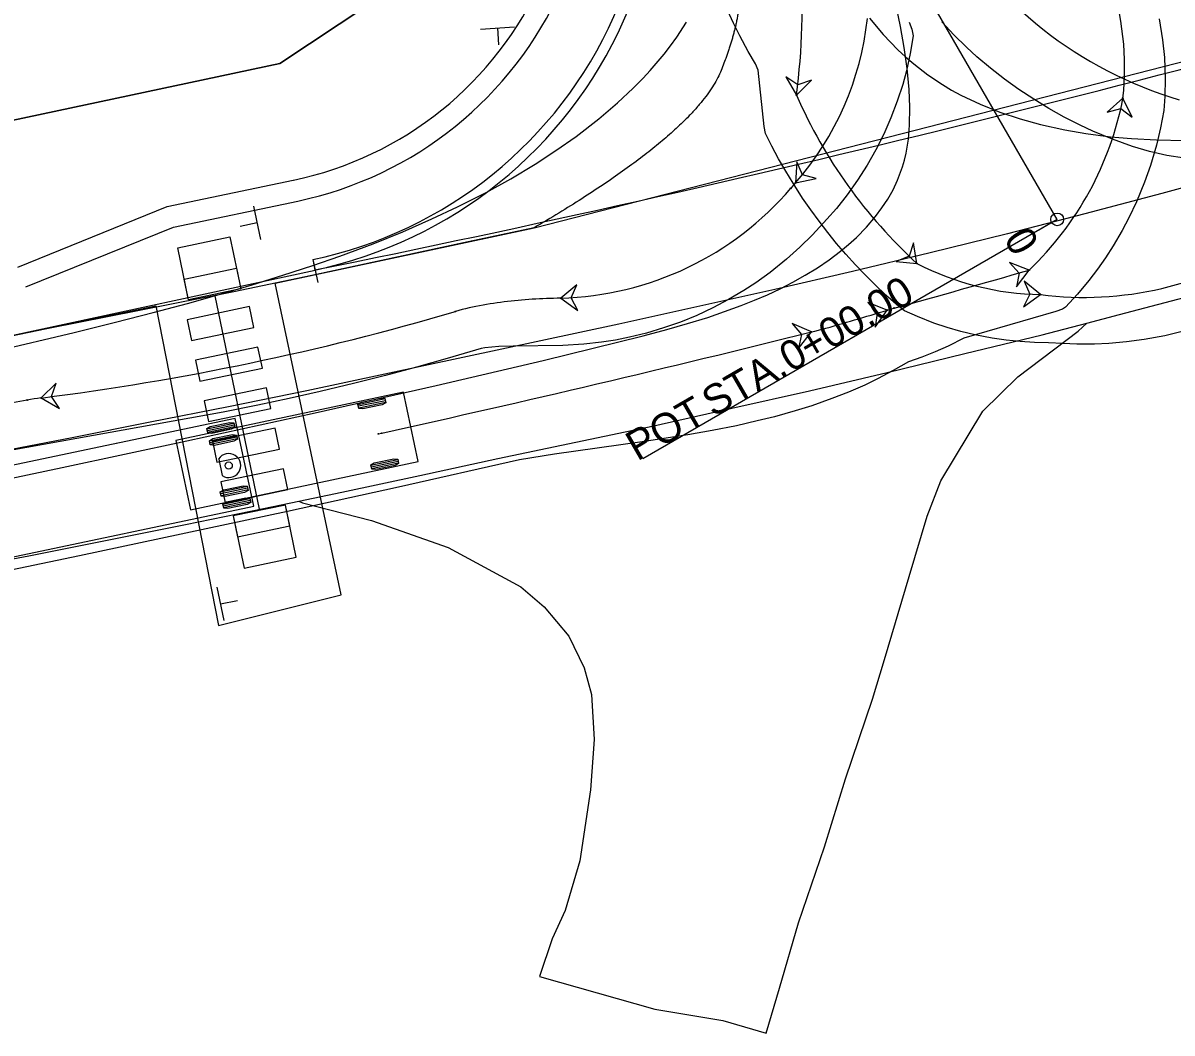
# Model space of a CAD drawing. Extents: x 208278 to 2196496, y 417130 to 637870.
# Drawn here: x 209106 to 209214, y 417248.4 to 417343.4 of the extents above; entities that cross this region are included whole.
import ezdxf

# ---------------------------------------------------------------- set-up
doc = ezdxf.new("R2010")
doc.units = 0
for name, color, linetype in [('BR_P_Beam', 7, 'Continuous'), ('DR_P_Ditch', 7, 'Continuous'), ('DR_P_Filter_Fabric_Fence', 7, 'Continuous'), ('DR_P_Trench_Drain', 7, 'Continuous'), ('LT_P_Conduit', 7, 'Continuous'), ('PM_P_Channelizing_Line', 7, 'Continuous'), ('PM_P_CL_Dashed', 7, 'Continuous'), ('PM_P_Crosswalk', 7, 'Continuous'), ('PM_P_Edge_Line', 7, 'Continuous'), ('PV_P_Curb', 7, 'Continuous'), ('RD_P_Concrete_Barrier', 7, 'Continuous'), ('RD_P_Fence', 7, 'Continuous'), ('RD_P_Gate', 7, 'Continuous'), ('RW_P_PARCEL', 7, 'Continuous'), ('UT_P_Sanitary', 7, 'Continuous'), ('UT_P_Water', 7, 'Continuous'), ('XS_P_Section', 7, 'Continuous')]:
    doc.layers.add(name, color=color, linetype=linetype)

msp = doc.modelspace()

# ---------------------------------------------------------------- linework, layer by layer
at = {"layer": 'BR_P_Beam'}
msp.add_arc((209125.04, 417360.3), 41, 281.847, 30.029, dxfattribs=at)
at = {"layer": 'DR_P_Ditch'}
msp.add_line((209203.23, 417324.93), (209161.75, 417396.69), dxfattribs=at)
at = {"layer": 'DR_P_Filter_Fabric_Fence'}
for points in [[(209103.37, 417312.55), (209110.83, 417314.3), (209114.71, 417315.26), (209118.26, 417316.17), (209121.48, 417317.04), (209124.69, 417317.94), (209127.57, 417318.79), (209130.43, 417319.68), (209133.28, 417320.61), (209135.8, 417321.49), (209138.93, 417322.65), (209141.71, 417323.77), (209144.46, 417324.97), (209146.87, 417326.1), (209149.55, 417327.46), (209151.88, 417328.75), (209154.17, 417330.13), (209156.12, 417331.4), (209158.03, 417332.74), (209160.14, 417334.38), (209161.91, 417335.89), (209163.37, 417337.26), (209164.3, 417338.21), (209164.98, 417338.94), (209166.28, 417340.47), (209166.89, 417341.25), (209167.47, 417342.06), (209168.39, 417343.46)], [(209189.33, 417343.46), (209189.56, 417342.83), (209189.7, 417342.18), (209189.42, 417340.54), (209189.06, 417338.91), (209188.71, 417337.62), (209188.2, 417336.04), (209187.6, 417334.48), (209186.93, 417332.95), (209186.19, 417331.47), (209185.36, 417330.02), (209184.47, 417328.61), (209183.5, 417327.25), (209182.47, 417325.95), (209181.59, 417324.94), (209180.23, 417323.48), (209179.04, 417322.31), (209177.8, 417321.19), (209176.24, 417319.94), (209174.89, 417318.97), (209173.77, 417318.24), (209172.34, 417317.39), (209170.87, 417316.61), (209169.36, 417315.91), (209167.81, 417315.28), (209166.24, 417314.73), (209164.64, 417314.25), (209163.03, 417313.85), (209161.72, 417313.59), (209160.4, 417313.39), (209158.75, 417313.2), (209156.75, 417313.08), (209152.08, 417313.03), (209150.75, 417312.97), (209149.42, 417312.87), (209149.1, 417312.8), (209145.9, 417311.85), (209143.01, 417311.04), (209140.11, 417310.27), (209137.21, 417309.53), (209133.96, 417308.76), (209131.04, 417308.1), (209128.1, 417307.48), (209124.83, 417306.82), (209104.82, 417303.22)], [(209178.64, 417328.37), (209180.57, 417328.77), (209179.28, 417329.11), (209178.75, 417330.34), (209178.64, 417328.37)], [(209178.64, 417328.37), (209178.42, 417328.12), (209178.2, 417327.86)], [(209156.56, 417317.53), (209158.16, 417316.38), (209157.54, 417317.56), (209158.08, 417318.78), (209156.56, 417317.53)], [(209156.56, 417317.53), (209156.22, 417317.52), (209155.89, 417317.51), (209155.56, 417317.5), (209155.22, 417317.49), (209154.89, 417317.47), (209154.56, 417317.46), (209154.22, 417317.44), (209153.89, 417317.42), (209153.56, 417317.4), (209153.23, 417317.37), (209152.89, 417317.35), (209152.56, 417317.32), (209152.23, 417317.29), (209151.9, 417317.25), (209151.57, 417317.22), (209151.24, 417317.18), (209150.91, 417317.13), (209150.58, 417317.09), (209150.25, 417317.04), (209149.92, 417316.99), (209149.59, 417316.93), (209149.26, 417316.88), (209148.93, 417316.81), (209148.6, 417316.75), (209148.28, 417316.68), (209147.95, 417316.61), (209147.63, 417316.53), (209147.31, 417316.45), (209146.98, 417316.36), (209146.66, 417316.27)], [(209107.73, 417308.15), (209109.44, 417307.15), (209108.71, 417308.27), (209109.13, 417309.54), (209107.73, 417308.15)], [(209107.73, 417308.15), (209107.4, 417308.1), (209107.07, 417308.06), (209106.74, 417308.01), (209106.41, 417307.95)]]:
    msp.add_lwpolyline(points, dxfattribs=at)
for points in [[(209178.64, 417328.37), (209180.57, 417328.77), (209179.28, 417329.11), (209178.75, 417330.34)], [(209156.56, 417317.53), (209158.16, 417316.38), (209157.54, 417317.56), (209158.08, 417318.78)], [(209107.73, 417308.15), (209109.44, 417307.15), (209108.71, 417308.27), (209109.13, 417309.54)]]:
    msp.add_lwpolyline(points, close=True, dxfattribs=at)
for centre in [(209178.2, 417327.86), (209178.2, 417327.86), (209178.64, 417328.37), (209178.64, 417328.37), (209156.56, 417317.53), (209156.56, 417317.53), (209146.66, 417316.27), (209146.66, 417316.27), (209107.73, 417308.15), (209107.73, 417308.15), (209106.41, 417307.95), (209106.41, 417307.95)]:
    msp.add_circle(centre, 0.0417, dxfattribs=at)
for centre, radius, start, end in [((209157.52, 417346.8), 28.03, 318.8875, 353.8854), ((209155.75, 417347.05), 29.53, 271.5616, 319.4785), ((209076.23, 417556.4), 250.25, 277.2308, 286.3462), ((210285.7, 410968.14), 6448.56, 100.537372, 101.036132)]:
    msp.add_arc(centre, radius, start, end, dxfattribs=at)
at = {"layer": 'DR_P_Trench_Drain'}
msp.add_lwpolyline([(209215.18, 417330.69), (209213.53, 417330.94), (209211.91, 417331.31), (209210.31, 417331.78), (209208.43, 417332.47), (209206.59, 417333.24), (209205.38, 417333.8), (209203.89, 417334.55), (209202.44, 417335.36), (209201.02, 417336.23), (209199.63, 417337.15), (209198.28, 417338.13), (209196.96, 417339.16), (209195.69, 417340.23), (209194.71, 417341.13), (209193.51, 417342.29), (209192.37, 417343.5)], dxfattribs=at)
msp.add_arc((209225.78, 417373.22), 38.67, 210.338, 253.3438, dxfattribs=at)
at = {"layer": 'LT_P_Conduit'}
for points in [[(209214.98, 417314.38), (209213.36, 417313.99), (209211.4, 417313.63), (209209.74, 417313.41), (209208.08, 417313.27), (209206.75, 417313.21), (209205.08, 417313.2), (209203.75, 417313.25), (209202.42, 417313.34), (209201.09, 417313.37), (209199.76, 417313.44), (209198.43, 417313.57), (209197.11, 417313.76), (209195.48, 417314.08), (209194.18, 417314.39), (209192.9, 417314.76), (209191.64, 417315.19), (209190.09, 417315.79), (209188.87, 417316.34), (209188.34, 417316.74), (209187.34, 417317.62), (209186.36, 417318.53), (209185.18, 417319.71), (209184.26, 417320.67), (209183.37, 417321.66), (209182.5, 417322.67), (209181.66, 417323.71), (209180.85, 417324.76), (209180.06, 417325.84), (209179.3, 417326.94), (209178.4, 417328.34), (209177.71, 417329.48), (209177.04, 417330.63), (209176.41, 417331.81), (209175.81, 417333), (209175.69, 417333.65), (209175.13, 417338.96), (209174.87, 417339.57), (209174.19, 417340.72), (209173.4, 417342.18), (209172.81, 417343.38), (209172.24, 417344.59)], [(209185.58, 417343.86), (209186.87, 417342.32), (209187.55, 417341.59), (209188.25, 417340.88), (209188.98, 417340.2), (209189.74, 417339.55), (209191.06, 417338.53), (209192.44, 417337.6), (209193.3, 417337.09), (209194.18, 417336.62), (209195.99, 417335.76), (209197.84, 417335.01), (209199.74, 417334.38), (209201.66, 417333.84), (209203.94, 417333.34), (209205.91, 417333), (209208.23, 417332.7), (209210.22, 417332.53), (209212.55, 417332.41), (209215.22, 417332.36)], [(209178.72, 417336.61), (209180.12, 417338.01), (209178.85, 417337.59), (209177.73, 417338.32), (209178.72, 417336.61)], [(209190.04, 417320.79), (209189.71, 417322.74), (209189.32, 417321.46), (209188.08, 417320.97), (209190.04, 417320.79)], [(209201.65, 417317.87), (209200.12, 417319.11), (209200.67, 417317.89), (209200.06, 417316.7), (209201.65, 417317.87)]]:
    msp.add_lwpolyline(points, dxfattribs=at)
for points in [[(209178.72, 417336.61), (209180.12, 417338.01), (209178.85, 417337.59), (209177.73, 417338.32)], [(209190.04, 417320.79), (209189.71, 417322.74), (209189.32, 417321.46), (209188.08, 417320.97)], [(209201.65, 417317.87), (209200.12, 417319.11), (209200.67, 417317.89), (209200.06, 417316.7)]]:
    msp.add_lwpolyline(points, close=True, dxfattribs=at)
for centre in [(209178.72, 417336.61), (209178.72, 417336.61), (209190.04, 417320.79), (209190.04, 417320.79), (209201.65, 417317.87), (209201.65, 417317.87)]:
    msp.add_circle(centre, 0.0417, dxfattribs=at)
for centre, radius, start, end in [((209117.29, 417344.79), 61.97, 352.412, 16.2407), ((209221.9, 417355.55), 47.15, 203.6848, 227.4956), ((209205.77, 417349.42), 31.82, 262.5686, 303.9316), ((209202.11, 417344.17), 26.31, 242.7082, 269.0122)]:
    msp.add_arc(centre, radius, start, end, dxfattribs=at)
at = {"layer": 'PM_P_Channelizing_Line'}
for points in [[(209125.46, 417323.28), (209126.49, 417318.39), (209121.59, 417317.36), (209120.57, 417322.26)], [(209126.08, 417320.34), (209126.49, 417318.39), (209121.59, 417317.36), (209121.18, 417319.32)], [(209131.7, 417293.17), (209130.69, 417298.07), (209125.79, 417297.05), (209126.81, 417292.16)], [(209131.09, 417296.11), (209130.69, 417298.07), (209125.79, 417297.05), (209126.2, 417295.09)]]:
    msp.add_lwpolyline(points, close=True, dxfattribs=at)
at = {"layer": 'PM_P_CL_Dashed'}
for points in [[(209121.85, 417313.54), (209127.73, 417314.77), (209127.32, 417316.73), (209121.44, 417315.5)], [(209122.65, 417309.73), (209128.52, 417310.96), (209128.11, 417312.92), (209122.24, 417311.69)], [(209123.45, 417305.92), (209129.32, 417307.15), (209128.91, 417309.11), (209123.04, 417307.88)], [(209124.24, 417302.11), (209130.12, 417303.34), (209129.71, 417305.3), (209123.83, 417304.07)], [(209125.04, 417298.3), (209130.91, 417299.53), (209130.5, 417301.49), (209124.63, 417300.26)]]:
    msp.add_lwpolyline(points, close=True, dxfattribs=at)
at = {"layer": 'PM_P_Crosswalk'}
for p, q in [((209149.02, 417342.83), (209152.22, 417343.02)), ((209150.62, 417342.93), (209150.72, 417341.33)), ((209150.62, 417342.93), (209150.62, 417342.93)), ((209127.69, 417326.17), (209128.35, 417323.03)), ((209128.02, 417324.6), (209126.45, 417324.27)), ((209128.02, 417324.6), (209128.02, 417324.6)), ((209124.93, 417287.21), (209124.28, 417290.35)), ((209124.6, 417288.78), (209126.17, 417289.11)), ((209124.6, 417288.78), (209124.6, 417288.78))]:
    msp.add_line(p, q, dxfattribs=at)
at = {"layer": 'PM_P_Edge_Line'}
msp.add_lwpolyline([(209093.86, 417513.4), (209102.11, 417463.85), (209121.09, 417416.38), (209142.14, 417379.63), (209146.67, 417363.53), (209141.31, 417347.02), (209130.17, 417339.58), (209102, 417333.59), (209104.94, 417313.99), (209118.52, 417316.8), (209124.41, 417286.75), (209135.92, 417289.64), (209129.73, 417318.94), (209154.07, 417324.14), (209248.91, 417348.5), (209255.78, 417350.71), (209251.98, 417364.94), (209222.73, 417364.32), (209215.99, 417362.52), (209193.28, 417384.78), (209187.97, 417395.34), (209174.69, 417434.86), (209154.88, 417469.95), (209142.09, 417520.32)], dxfattribs=at)
at = {"layer": 'PV_P_Curb'}
msp.add_lwpolyline([(209220.31, 417329.34), (209213.07, 417327.38), (209205.82, 417325.47), (209198.56, 417323.58), (209191.28, 417321.8), (209183.99, 417320.03), (209176.68, 417318.34), (209169.36, 417316.7), (209162.04, 417315.07), (209154.7, 417313.53), (209147.37, 417311.96), (209140.03, 417310.39), (209132.7, 417308.82), (209125.35, 417307.32), (209117.99, 417305.86), (209110.64, 417304.41), (209103.27, 417303)], dxfattribs=at)
at = {"layer": 'RD_P_Concrete_Barrier'}
for points in [[(209154.07, 417324.14), (209147.85, 417322.81), (209133.18, 417319.66), (209125.84, 417318.12), (209111.13, 417315.21), (209103.77, 417313.77), (209081.63, 417309.75), (209074.24, 417308.49), (209066.84, 417307.25), (209059.45, 417305.98), (209029.89, 417300.86), (209022.5, 417299.55), (208992.99, 417294.18), (208985.61, 417292.83), (208978.22, 417291.53), (208948.67, 417286.39), (208941.28, 417285.1), (208904.33, 417278.7), (208896.95, 417277.38), (208867.41, 417272.13), (208860.03, 417270.8), (208793.63, 417258.66), (208786.25, 417257.31), (208778.88, 417255.94)], [(209099.21, 417291.93), (209106.58, 417293.3), (209113.94, 417294.77), (209121.29, 417296.26), (209128.63, 417297.76), (209131.94, 417298.45), (209135.98, 417299.29), (209143.31, 417300.87), (209150.64, 417302.44), (209157.98, 417304), (209165.32, 417305.54), (209172.64, 417307.18), (209179.96, 417308.82), (209187.26, 417310.53), (209194.54, 417312.31), (209201.83, 417314.08), (209206.01, 417315.18), (209209.08, 417315.99), (209216.34, 417317.9)], [(209131.94, 417298.45), (209132.29, 417298.29), (209138.78, 417296.62), (209145.98, 417294.09), (209152.83, 417290.4), (209155.01, 417288.51), (209157.33, 417285.76), (209158.77, 417282.78), (209159.47, 417280.28), (209159.71, 417276.03), (209159.35, 417271.3), (209158.35, 417264.63), (209156.97, 417259.97), (209155.75, 417257.31), (209154.58, 417253.77), (209165.42, 417250.68), (209171.81, 417249.63), (209175.86, 417248.44), (209177.13, 417252.67), (209178.91, 417258.8), (209181.37, 417265.95), (209183.32, 417272.35), (209185.88, 417279.84), (209187.01, 417283.56), (209189.33, 417291.37), (209191.01, 417297.04), (209192.29, 417300.36), (209196.25, 417306.89), (209199.54, 417310.13), (209205.2, 417314.43), (209206.01, 417315.18)]]:
    msp.add_lwpolyline(points, dxfattribs=at)
msp.add_open_spline([(208609.05, 418791.74), (208754.84, 418615.78), (208765.24, 418602.84), (208786.46, 418576.01), (208805.09, 418552.36), (208822.06, 418531.18), (208839.68, 418510.58), (208850.53, 418496.21), (208868.33, 418473.16), (208885.98, 418449.74), (208901.76, 418429.46), (208923.53, 418401.55), (208946.91, 418370.95), (208973.19, 418337.11), (208998.37, 418302.71), (209011.82, 418283.75), (209029.87, 418257.68), (209043.7, 418235.61), (209066.13, 418198.05), (209073.85, 418182.85), (209084.25, 418161.82), (209095.54, 418134.5), (209105.49, 418106.74), (209112.75, 418083.23), (209118.4, 418061.3), (209125.65, 418028.96), (209131.8, 418004.65), (209135.32, 417980.96), (209140.18, 417952.97), (209143.43, 417932.17), (209146.71, 417910.42), (209149.06, 417894.12), (209152.03, 417869.62), (209153.49, 417849.93), (209154.1, 417829.36), (209154.52, 417812.83), (209153.97, 417793.32), (209152.56, 417777.57), (209149.95, 417760.2), (209147.7, 417748.06), (209143.21, 417727.93), (209137.45, 417707.72), (209132.12, 417689.59), (209126.06, 417672.9), (209115.97, 417648.15), (209109.02, 417628.62), (209106.47, 417617.02), (209104.98, 417608.71), (209104.45, 417598.01), (209104.31, 417580.42), (209105.49, 417557.54), (209107.29, 417538.08), (209110.88, 417513.39), (209122.57, 417470.17), (209132.91, 417432.97), (209150.06, 417393.82), (209161.49, 417373.71), (209168.97, 417360.7), (209172.4, 417352.45), (209174.02, 417344.77), (209169.23, 417333.02), (209154.07, 417324.14)], degree=2, dxfattribs=at)
at = {"layer": 'RD_P_Fence'}
for p, q in [((209141.79, 417308.68), (209120.4, 417304.14)), ((209140.05, 417308.05), (209137.51, 417307.51)), ((209143.17, 417302.16), (209141.79, 417308.68)), ((209141.79, 417308.68), (209141.79, 417308.68)), ((209140.08, 417307.89), (209137.55, 417307.36)), ((209140.12, 417307.73), (209137.58, 417307.2)), ((209125.97, 417306.22), (209087.24, 417298.05)), ((209127.71, 417297.98), (209125.97, 417306.22)), ((209125.97, 417306.22), (209125.97, 417306.22)), ((209125.85, 417305.76), (209123.31, 417305.22)), ((209125.88, 417305.6), (209123.35, 417305.06)), ((209125.91, 417305.44), (209123.38, 417304.91)), ((209120.4, 417304.14), (209121.78, 417297.63)), ((209126.09, 417304.62), (209123.55, 417304.08)), ((209126.12, 417304.46), (209123.59, 417303.92)), ((209126.16, 417304.3), (209123.62, 417303.76)), ((209121.78, 417297.63), (209143.17, 417302.16)), ((209124.42, 417302.4), (209124.75, 417300.85)), ((209141.26, 417302.34), (209138.72, 417301.81)), ((209141.29, 417302.18), (209138.76, 417301.65)), ((209141.33, 417302.03), (209138.79, 417301.49)), ((209127.11, 417299.82), (209124.57, 417299.28)), ((209127.14, 417299.66), (209124.61, 417299.12)), ((209127.18, 417299.5), (209124.64, 417298.96)), ((209127.35, 417298.67), (209124.81, 417298.14)), ((209127.38, 417298.52), (209124.85, 417297.98)), ((209127.42, 417298.36), (209124.88, 417297.82)), ((209088.98, 417289.82), (209127.71, 417297.98))]:
    msp.add_line(p, q, dxfattribs=at)
for points in [[(209086.87, 417296.78), (209109.69, 417301.61), (209121.43, 417304.12), (209133.47, 417306.76), (209144.85, 417309.32), (209154.91, 417311.68), (209164.3, 417313.99), (209166.55, 417314.59), (209168.48, 417315.14), (209170.39, 417315.72), (209171.97, 417316.26), (209173.53, 417316.83), (209174.77, 417317.33), (209176, 417317.85), (209177.2, 417318.42), (209178.39, 417319.03), (209179.55, 417319.68), (209180.69, 417320.37), (209181.79, 417321.12), (209182.86, 417321.93), (209183.62, 417322.57), (209184.36, 417323.24), (209185.29, 417324.2), (209186.16, 417325.21), (209186.76, 417326.01), (209187.31, 417326.84), (209187.8, 417327.71), (209188.23, 417328.62), (209188.7, 417329.86), (209188.89, 417330.5), (209189.03, 417331.15), (209189.24, 417332.47), (209189.35, 417333.8), (209189.39, 417335.47), (209189.32, 417337.13), (209189.14, 417339.12), (209188.86, 417341.1), (209188.51, 417343.07), (209188.09, 417345.03)], [(209212.81, 417343.79), (209213.13, 417341.82), (209213.3, 417340.16), (209213.38, 417338.17), (209213.35, 417336.5), (209213.25, 417335.17), (209212.95, 417333.53), (209212.57, 417331.91), (209212, 417329.99), (209211.45, 417328.42), (209210.69, 417326.57), (209209.97, 417325.07), (209209.34, 417323.89), (209208.5, 417322.45), (209207.78, 417321.33), (209207.01, 417320.24), (209206.2, 417319.18), (209205.14, 417317.9), (209204.01, 417316.67), (209203.73, 417316.49), (209203.11, 417316.26), (209194.46, 417313.77), (209192.97, 417313.02), (209191.76, 417312.47), (209190.52, 417311.98), (209189.26, 417311.54), (209187.81, 417310.72), (209186.34, 417309.94), (209185.14, 417309.36), (209183.61, 417308.69), (209182.06, 417308.08), (209180.17, 417307.42), (209178.59, 417306.92), (209176.66, 417306.38), (209175.04, 417305.98), (209173.09, 417305.54), (209170.8, 417305.09), (209168.51, 417304.68), (209164.22, 417304.01), (209155.97, 417302.86), (209152.69, 417302.32), (209141.31, 417299.76), (209130.88, 417297.48), (209111.32, 417293.31), (209088.49, 417288.53)], [(209209.4, 417336.32), (209207.92, 417335.01), (209209.21, 417335.35), (209210.28, 417334.55), (209209.4, 417336.32)], [(209200.59, 417320.17), (209198.75, 417320.89), (209199.64, 417319.89), (209199.41, 417318.58), (209200.59, 417320.17)], [(209187.26, 417316.41), (209185.42, 417317.11), (209186.32, 417316.13), (209186.11, 417314.81), (209187.26, 417316.41)], [(209187.26, 417316.41), (209187.58, 417316.51), (209187.9, 417316.6)], [(209180.13, 417314.35), (209178.33, 417315.13), (209179.18, 417314.11), (209178.91, 417312.8), (209180.13, 417314.35)], [(209180.13, 417314.35), (209180.46, 417314.43), (209180.78, 417314.51), (209181.1, 417314.6)], [(209139.42, 417304.77), (209139.75, 417304.84)]]:
    msp.add_lwpolyline(points, dxfattribs=at)
for points in [[(209209.4, 417336.32), (209207.92, 417335.01), (209209.21, 417335.35), (209210.28, 417334.55)], [(209200.59, 417320.17), (209198.75, 417320.89), (209199.64, 417319.89), (209199.41, 417318.58)], [(209187.26, 417316.41), (209185.42, 417317.11), (209186.32, 417316.13), (209186.11, 417314.81)], [(209180.13, 417314.35), (209178.33, 417315.13), (209179.18, 417314.11), (209178.91, 417312.8)], [(209140.04, 417308.09), (209140.12, 417307.7), (209139.79, 417307.5), (209137.97, 417307.11), (209137.59, 417307.16), (209137.5, 417307.55), (209137.83, 417307.75), (209139.66, 417308.13)], [(209125.84, 417305.8), (209125.92, 417305.4), (209125.59, 417305.21), (209123.77, 417304.82), (209123.39, 417304.87), (209123.3, 417305.26), (209123.63, 417305.46), (209125.46, 417305.84)], [(209126.08, 417304.66), (209126.17, 417304.26), (209125.84, 417304.07), (209124.01, 417303.68), (209123.63, 417303.73), (209123.55, 417304.12), (209123.88, 417304.32), (209125.7, 417304.7)], [(209141.25, 417302.38), (209141.33, 417301.99), (209141, 417301.79), (209139.18, 417301.41), (209138.8, 417301.45), (209138.71, 417301.85), (209139.04, 417302.04), (209140.87, 417302.43)], [(209127.1, 417299.86), (209127.18, 417299.46), (209126.85, 417299.27), (209125.03, 417298.88), (209124.65, 417298.92), (209124.56, 417299.32), (209124.89, 417299.51), (209126.72, 417299.9)], [(209127.34, 417298.71), (209127.43, 417298.32), (209127.1, 417298.12), (209125.27, 417297.74), (209124.89, 417297.78), (209124.81, 417298.18), (209125.14, 417298.37), (209126.96, 417298.76)]]:
    msp.add_lwpolyline(points, close=True, dxfattribs=at)
for centre, radius in [((209209.4, 417336.32), 0.0417), ((209209.4, 417336.32), 0.0417), ((209200.59, 417320.17), 0.0417), ((209200.59, 417320.17), 0.0417), ((209187.26, 417316.41), 0.0417), ((209187.26, 417316.41), 0.0417), ((209187.9, 417316.6), 0.0417), ((209187.9, 417316.6), 0.0417), ((209181.1, 417314.6), 0.0417), ((209181.1, 417314.6), 0.0417), ((209180.13, 417314.35), 0.0417), ((209180.13, 417314.35), 0.0417), ((209139.42, 417304.77), 0.0417), ((209139.75, 417304.84), 0.0417), ((209139.75, 417304.84), 0.0417), ((209125.36, 417301.79), 0.337)]:
    msp.add_circle(centre, radius, dxfattribs=at)
for centre, radius, start, end in [((209183.32, 417339.2), 26.25, 353.6887, 44.304), ((209179.7, 417342.06), 30.26, 313.6601, 349.0623), ((208884.48, 418419.88), 1144.25, 285.37712, 286.0368), ((209081.99, 417664.01), 363.2, 285.8365, 286.8498), ((208798.65, 418844.29), 1576.78, 282.49304, 284.00082), ((209125.36, 417301.79), 1.13, 236.971, 146.971)]:
    msp.add_arc(centre, radius, start, end, dxfattribs=at)
at = {"layer": 'RD_P_Gate'}
for p, q in [((209133.25, 417321.15), (209133.75, 417318.99)), ((209133.25, 417321.15), (209133.45, 417320.17)), ((209124.04, 417317.75), (209128.23, 417297.68))]:
    msp.add_line(p, q, dxfattribs=at)
msp.add_lwpolyline([(209133.48, 417320.18), (209133.49, 417320.12), (209104.94, 417313.99), (209102, 417333.59), (209130.17, 417339.58), (209141.31, 417347.02), (209146.67, 417363.53), (209142.14, 417379.63), (209121.09, 417416.38), (209102.11, 417463.85), (209093.86, 417513.4), (209077.36, 417540.64), (209075.71, 417569.13), (209083.96, 417601.33), (209099.64, 417638.9), (209116.52, 417712.94), (209135.81, 417768.51), (209128.05, 417923.36), (209113.83, 417964.31), (209091.1, 417973.97), (209091.11, 417980.42), (209096.3, 417996.46), (209095.35, 418024.77)], dxfattribs=at)
for centre, radius, start, end in [((209125.04, 417360.3), 40, 281.847, 30.029), ((209125.04, 417360.3), 40, 281.847, 30.029), ((208835.85, 418789.42), 1499.08, 281.4508, 286.19452), ((208835.85, 418789.42), 1499.08, 281.4508, 281.45168)]:
    msp.add_arc(centre, radius, start, end, dxfattribs=at)
at = {"layer": 'RW_P_PARCEL'}
for p, q in [((209119.57, 417326.14), (209131.43, 417328.61)), ((209120.16, 417324.21), (209131.84, 417326.66)), ((209105.53, 417320.44), (209119.57, 417326.14)), ((209106.28, 417318.59), (209120.16, 417324.21))]:
    msp.add_line(p, q, dxfattribs=at)
for radius in [35, 33]:
    msp.add_arc((209124.68, 417360.92), radius, 281.8077, 30.029, dxfattribs=at)
at = {"layer": 'UT_P_Sanitary'}
msp.add_line((209203.23, 417324.93), (209164.27, 417302.41), dxfattribs=at)
msp.add_circle((209203.23, 417324.93), 0.6, dxfattribs=at)
at = {"layer": 'UT_P_Water'}
msp.add_arc((209125.04, 417360.3), 40, 281.847, 30.029, dxfattribs=at)
at = {"layer": 'XS_P_Section'}
msp.add_line((209203.23, 417324.93), (209201.5, 417323.93), dxfattribs=at)

# ---------------------------------------------------------------- texts
at = {"layer": 'UT_P_Sanitary'}
for s, p in [('0+00.00', (209178.18, 417310.5)), (' STA. ', (209170, 417305.77)), ('POT', (209163.76, 417302.16))]:
    msp.add_text(s, height=2.8, rotation=30.029, dxfattribs=at).set_placement(p)
at = {"layer": 'XS_P_Section'}
msp.add_text('0', height=2.8, rotation=120.029, dxfattribs=at).set_placement((209201.62, 417322.71))

doc.saveas('drawing.dxf')
